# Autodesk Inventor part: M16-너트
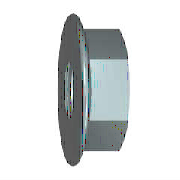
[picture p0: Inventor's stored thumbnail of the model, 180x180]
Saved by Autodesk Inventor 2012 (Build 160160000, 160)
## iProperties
IsCustomPart: 0
Company: 한국ATC센터
Created: 2009-02
Part Number: M16-너트
Material: Steel, Mild
Description: 플랜지붙이 6각 너트
Document SubType Name: Modeling
Standard: JIS B 1190
Designer: KYOUNG IL JANG
Standards Organization: JIS
Language: ko-KR
Size Designation: M 16
Categories: <MemberInstance><Categories><Category DisplayName="조임쇠" InternalName="e4da775c-781d-43d5-af7c-5136215cf5a6" Mnemonic="FSTN"><Category DisplayName="너트" InternalN
Density: 1 g/cm^3
Author: KYOUNG IL JANG
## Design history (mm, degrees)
workaxis "Work Axis1"
workplane "Work Plane1"
revolve "링" stored, may be unused: angle "d8" = 90 deg
sketch "스케치2"
  geometry: L1 (-11, -6.351)-(-11, 6.351); L2 (-11, 6.351)-(0, 12.702); L3 (0, 12.702)-(11, 6.351); L4 (11, 6.351)-(11, -6.351); L5 (11, -6.351)-(0, -12.702); L6 (0, -12.702)-(-11, -6.351); C1 r 4.9 at (0, 0); C2 r 14.7 at (0, 0) reference; 1 further point
  constraints: 12 end point, 1 centre point, 1 coincident, 1 vertical, 11 other
  dimensions: "d6" = 25.40341 distance of L5.end L2.end (= 1.1547 x SW)
extrude "본체" join sketch "스케치2" distance "d7" = 15 (= KOH); taper "d9" = 0 deg
revolve "모따기1" stored, may be unused: angle "d24" = 90 deg
sketch "스케치4"
  geometry: C1 r 14.7 at (0, 0) reference; 1 further point
  constraints: 1 coincident
hole "스레드" sketch "스케치4" diameter "d25" = 13.835; stored, may be unused: countersink angle "d29" = 82 deg, drill point angle "d31" = 118 deg; dims "d26" = 6, "d27" = 4, "d28" = 2, "d30" = 8
body "Solid1"
chamfer "모따기2" distance "d12" = 1.08253 (= -0.5 x GD1 + 0.5 x NND); stored, may be unused: angle "d13" = 30 deg, second distance "d46" = 1.08253 (= -0.5 x GD1 + 0.5 x NND)
chamfer "모따기3" distance "d51" = 1.08253 (= -0.5 x GD1 + 0.5 x NND); stored, may be unused: second distance "d52" = 2, angle "d53" = 45 deg
sketch "스케치1"
  geometry: L1 (-3.414, 0)-(18.069, 0) reference; L2 (6.015, 11)-(3.359, 15.6); L3 (6.015, 11)-(15, 11); L4 (15, 11)-(15, 0); L5 (6.015, 11)-(6.015, 0); L6 (0, -3.378)-(0, 20.266) reference; A1 r 1.8 centre (1.8, 14.7) between (3.359, 15.6) and (0, 14.7); 1 further point
  constraints: 8 end point, 3 point on line, 2 perpendicular, 2 point on circle, 2 tangent, 1 centre point, 1 parallel
  dimensions: "d2" = 22 diameter of L3 L1 (= SW); "d4" = 33 dimension on A1 L1 (= LADI); "d5" = 1.8 radius of A1 (= PHH); "d15" = 15 distance between parallel lines of L4 L6 (= KOH); "d16" = 30 deg angle of L6 L2 (= KEWI)
sketch "스케치3"
  geometry: L1 (5.032, 12.702)-(15, 12.702) reference; L2 (15, 6.351)-(15, 12.702) reference; L3 (0, -14.7)-(0, 14.7) reference; L4 (-3, 0)-(18, 0) reference; L5 (14.018, 12.702)-(15, 11)
  constraints: 2 end point, 2 point on line
  dimensions: "d10" = 30 deg angle of L2 L5 (= ANG1); "d11" = 22 diameter of L5.end L4 (= SW0)
other parameters: "ANG1" = 30 deg [user parameter; used in 1 equation term], "KEWI" = 30 deg [user parameter; used in 1 equation term], "NND" = 16 [user parameter; used in 3 equation terms], "LADI" = 33 [user parameter; used in 2 equation terms], "SW" = 22 [user parameter; used in 4 equation terms], "PHH" = 1.8 [user parameter; used in 2 equation terms], "KOH" = 15 [user parameter; used in 2 equation terms], "SW0" = 22 (= SW) [user parameter; used in 1 equation term], "GD1" = 13.83494 (computed from THREADDIA, PTC, TOA) [user parameter; used in 3 equation terms], "d1" = 33 (= LADI), "d3" = 1.8 (= PHH), "d45" = 0, "d47" = 0, "d49" = 0, "d54" = 0, "GUL" = 1.08253 (= 0.541266 x PTC) [user parameter], "TPU" = 5 (computed from PTC) [user parameter], "RR" = 2 [user parameter], "THREADDIA" = 16 [user parameter; used in 1 equation term], "TOA" = 30 deg [user parameter; used in 1 equation term], "PTC" = 2 [user parameter; used in 4 equation terms], "GAL" = 1.08253 (= 0.541266 x PTC) [user parameter], "E0" = 25.41 (= 1.155 x SW) [user parameter]
